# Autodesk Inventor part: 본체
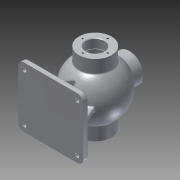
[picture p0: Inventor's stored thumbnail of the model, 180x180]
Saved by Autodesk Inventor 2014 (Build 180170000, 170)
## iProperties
Created: 2017-01
Part Number: 본체
Material: Aluminum 6061
Document SubType Name: Modeling
Designer: ksu
Density: 2.71 g/cm^3
Appearance: Aluminum - Flat
Mass: 1509.55 g
Surface Area: 1153.31 cm^2
Volume: 557.028 cm^3
Author: ksu
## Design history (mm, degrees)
sketch "Sketch1"
  geometry: L1 (0, -53)-(0, 53); A1 r 53 centre (0, 0) between (0, -53) and (0, 53); 1 further point
  constraints: 2 end point, 2 point on circle, 1 centre point, 1 coincident, 1 vertical
  dimensions: "d0" = 106 diameter of A1
revolve "Revolution1" sketch "Sketch1" stored, may be unused: angle "d1" = 90 deg
node "Sketch2"
workplane "Work Plane1"
sketch "Sketch3"
  geometry: C1 r 31 at (0, 0); 1 further point
  constraints: 1 centre point, 1 coincident
  dimensions: "d6" = 62 diameter of C1
extrude "Extrusion1" join sketch "Sketch3" distance "d7" = 27.4625; taper "d8" = 0 deg
node "Sketch4"
mirror "Mirror1"
sketch "Sketch5"
  geometry: C1 r 31 at (0, 0) reference; C2 r 17.5 at (0, 0)
  constraints: 1 centre point, 1 coincident
  dimensions: "d10" = 35 diameter of C2
extrude "Extrusion2" cut sketch "Sketch5" stored distance "d11" = 27.4625; taper "d12" = 0 deg
chamfer "Chamfer1" distance "d13" = 1; stored, may be unused: second distance "d14" = 2, angle "d15" = 45 deg
sketch "Sketch6"
  geometry: L1 (0, -43)-(0, 43); A1 r 43 centre (0, 0) between (0, -43) and (0, 43); 1 further point
  constraints: 2 end point, 2 point on circle, 1 centre point, 1 coincident, 1 vertical
  dimensions: "d16" = 86 diameter of A1
revolve "Revolution2" sketch "Sketch6" stored, may be unused: angle "d17" = 90 deg
sketch "Sketch7"
  geometry: L1 (52, -18.5)-(52, 0); L2 (50.25, -18.5)-(50.25, 0); L3 (50.25, -18.5)-(52, -18.5); L4 (50.25, 0)-(52, 0); 1 further point
  constraints: 8 end point, 2 parallel, 1 perpendicular
  dimensions: "d19" = 1.75 distance between parallel lines of L2 L1
revolve "Revolution3" sketch "Sketch7" stored, may be unused: angle "d21" = 90 deg
sketch "Sketch8"
  geometry: 4 further points
hole "Hole1" sketch "Sketch8" at (0, 22.5), (22.5, 0), (0, -22.5), (-22.5, 0) diameter "d23" = 3.242; stored, may be unused: countersink angle "d27" = 90 deg, drill point angle "d29" = 118 deg; dims "d24" = 12, "d25" = 4, "d26" = 2, "d28" = 15
sketch "Sketch9"
  geometry: 4 further points
hole "Hole2" sketch "Sketch9" at (0, 24), (24, 0), (-24, 0), (0, -24) diameter "d31" = 3.242; stored, may be unused: countersink angle "d35" = 90 deg, drill point angle "d37" = 118 deg; dims "d32" = 16, "d33" = 4, "d34" = 2, "d36" = 19
workplane "Work Plane2"
sketch "Sketch10"
  geometry: L1 (62.5, -57.5)-(-62.5, -57.5); L2 (-62.5, -57.5)-(-62.5, 57.5); L3 (-62.5, 57.5)-(62.5, 57.5); L4 (62.5, 57.5)-(62.5, -57.5); L5 (62.5, -57.5)-(-62.5, 57.5); L6 (-62.5, -57.5)-(62.5, 57.5); 1 further point
  constraints: 12 end point, 2 midpoint, 2 parallel, 1 horizontal, 1 perpendicular
  dimensions: "d83" = 125 distance of L2.end L3.end; "d84" = 115 distance of L1.end L2.end
extrude "Extrusion3" join sketch "Sketch10" distance "d44" = 10; taper "d45" = 0 deg
workplane "Work Plane3"
sketch "Sketch11"
  geometry: C1 r 27 at (0, 0); 1 further point
  constraints: 1 centre point, 1 coincident
  dimensions: "d48" = 54 diameter of C1
extrude "Extrusion4" join sketch "Sketch11" distance "d49" = 21.1125; taper "d50" = 0 deg
sketch "Sketch13"
  geometry: C1 r 27 at (0, 0) reference; C2 r 13 at (0, 0)
  constraints: 1 centre point, 1 coincident
  dimensions: "d51" = 26 diameter of C2
extrude "Extrusion5" cut sketch "Sketch13" distance "d52" = 36.9875; taper "d53" = 0 deg
sketch "Sketch14"
  geometry: 4 further points
hole "Hole3" sketch "Sketch14" at (0, 20), (20, 0), (0, -20), (-20, 0) diameter "d55" = 3.242; stored, may be unused: countersink angle "d59" = 90 deg, drill point angle "d61" = 118 deg; dims "d56" = 9, "d57" = 4, "d58" = 2, "d60" = 11
sketch "Sketch15"
  geometry: L1 (49.52, 80)-(31.635, 35.734); L2 (-49.52, 80)-(-31.635, 35.734); L3 (49.52, 80)-(-49.52, 80); A1 r 47.725 centre (0, 0) between (31.635, 35.734) and (-31.635, 35.734)
  constraints: 6 end point, 2 point on circle, 1 centre point
extrude "Extrusion6" join sketch "Sketch15" stored distance "d64" = 8; taper "d65" = 0 deg
sketch "Sketch16"
  geometry: L1 (-54.52, 80)-(-35.476, 32.865); L2 (54.52, 80)-(35.476, 32.865); L3 (-54.52, 80)-(54.52, 80); A1 r 48.36 centre (0, 0) between (35.476, 32.865) and (-35.476, 32.865)
  constraints: 6 end point, 2 point on circle, 1 centre point
extrude "Extrusion7" join sketch "Sketch16" stored distance "d68" = 8; taper "d69" = 0 deg
sketch "Sketch17"
  geometry: C1 r 6 at (-50.5, 45.5); C2 r 6 at (50.5, 45.5); C3 r 6 at (-50.5, -45.5); C4 r 6 at (50.5, -45.5)
  constraints: 4 centre point
  dimensions: "d89" = 12 diameter of C1
extrude "Extrusion8" cut sketch "Sketch17" distance "d73" = 3; taper "d74" = 0 deg
fillet "Fillet2" dims "d78" = 3
fillet "Fillet4" dims "d80" = 3
fillet "Fillet5" dims "d81" = 3
fillet "Fillet6" dims "d85" = 12
sketch "Sketch19"
  geometry: C1 r 6 at (0, 0) reference; C2 r 4 at (0, 0); 1 further point
  constraints: 1 centre point, 1 coincident
  dimensions: "d95" = 8 diameter of C2
extrude "Extrusion10" cut sketch "Sketch19" distance "d96" = 10; taper "d97" = 0 deg
mirror "Mirror5"
mirror "Mirror6"
fillet "Fillet7" dims "d98" = 3
fillet "Fillet8" dims "d101" = 3
fillet "Fillet9" dims "d102" = 3
fillet "Fillet10" dims "d103" = 3
fillet "Fillet11" dims "d106" = 3
fillet "Fillet12" dims "d107" = 3
workplane "Work Plane5"
sketch "Sketch20"
  geometry: L1 (20.739, -58.002)-(-20.739, -58.002); L2 (-20.739, -58.002)-(-20.739, -51.998); L3 (-20.739, -51.998)-(20.739, -51.998); L4 (20.739, -51.998)-(20.739, -58.002); L5 (-27, -65)-(27, -65) reference; L6 (27, -65)-(27, -47.286) reference; L7 (20.739, -55)-(-20.739, -55); L8 (0, -58.002)-(0, -51.998); 1 further point
  constraints: 4 end point, 4 midpoint, 2 other
  dimensions: "d109" = 27 distance between parallel lines of L6 L8; "d110" = 10 distance between parallel lines of L5 L7
emboss "Emboss1" sketch "Sketch20" dims "d0" = 106, "d111" = 0.5, "d112" = 0
body "Solid1"
other parameters: "d5" = 68, "d20" = 18.5, "d38" = 85, "d108" = -27
